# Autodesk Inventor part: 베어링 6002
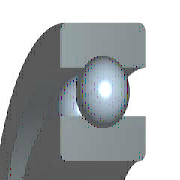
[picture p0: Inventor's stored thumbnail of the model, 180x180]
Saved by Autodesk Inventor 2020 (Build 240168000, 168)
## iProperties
Created: 2012-02
Part Number: 베어링 6002
Material: 강철, 연강
Description: 깊은 그루브 볼 베어링
Document SubType Name: Modeling
Standard: KS B 2023
Designer: mduedu
Standards Organization: KS
Language: ko-KR
Size Designation: 6002 - 15 x 32 x 9
Categories: <MemberInstance><Categories><Category DisplayName="샤프트 부품" InternalName="7f7aeb1f-a693-4053-b835-cee3144e0d98" Mnemonic="SHFT"><Category DisplayName="베어링" Inter
Density: 7.86 g/cm^3
Mass: 29.8124 g
Surface Area: 39.9079 cm^2
Volume: 3.79292 cm^3
Appearance: 분홍색
IsCustomPart: 1
Author: mduedu
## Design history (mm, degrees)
sketch "스케치" dims "d0" = 4.42 (= -0.26 x WD + 0.26 x BD)
  geometry: L1 (2.29, 11.75)-(6.71, 11.75); L2 (4.5, 11.75)-(4.5, 9.54); L3 (4.5, 11.75)-(4.5, 13.96); L4 (2.858, 10.271)-(0, 10.271); L5 (0, 7.5)-(9, 7.5); L6 (2.858, 13.229)-(0, 13.229); L7 (0, 16)-(9, 16); L8 (9, 7.5)-(9, 10.271); L9 (6.142, 10.271)-(9, 10.271); L10 (6.142, 13.229)-(9, 13.229); L11 (9, 16)-(9, 13.229); L12 (-1.4, 0)-(8.4, 0) reference; L13 (0, -0.3)-(0, 5.3) reference
  constraints: 22 end point, 4 point on line, 2 collinear, 2 perpendicular, 2 symmetric about line, 1 midpoint, 1 parallel, 14 other
  dimensions: "d9" = 15 diameter of L5 L12 (= WD); "d11" = 32 diameter of L7 L12 (= BD); "d12" = 9 distance between parallel lines of L8 L13 (= KB); "d13" = 20.542 diameter of L9 L12 (= 0.326 x BD + 0.674 x WD)
revolve "본체" stored, may be unused: angle "d6" = 90 deg
revolve "볼" stored, may be unused: angle "d7" = 90 deg
pattern_circular "IDS_ARRAYBALL[SIMPL:T]" dims angle "d3" = 360 deg
body "Solid1"
fillet "모깎기1" dims "d1" = 0.3 (= KRS)
other parameters: "WD" = 15 [user parameter; used in 5 equation terms], "BD" = 32 [user parameter; used in 5 equation terms], "KB" = 9 [user parameter; used in 1 equation term], "KRS" = 0.3 [user parameter; used in 1 equation term], "d4" = 0, "d5" = 0, "d8" = 0, "d14" = 0, "d15" = 0, "BBA" = 0 [user parameter], "BC0" = 2850000 [user parameter], "BC" = 5590000 [user parameter], "BR" = 16 (= 0.5 x BD) [user parameter], "WR" = 7.5 (= 0.5 x WD) [user parameter]
